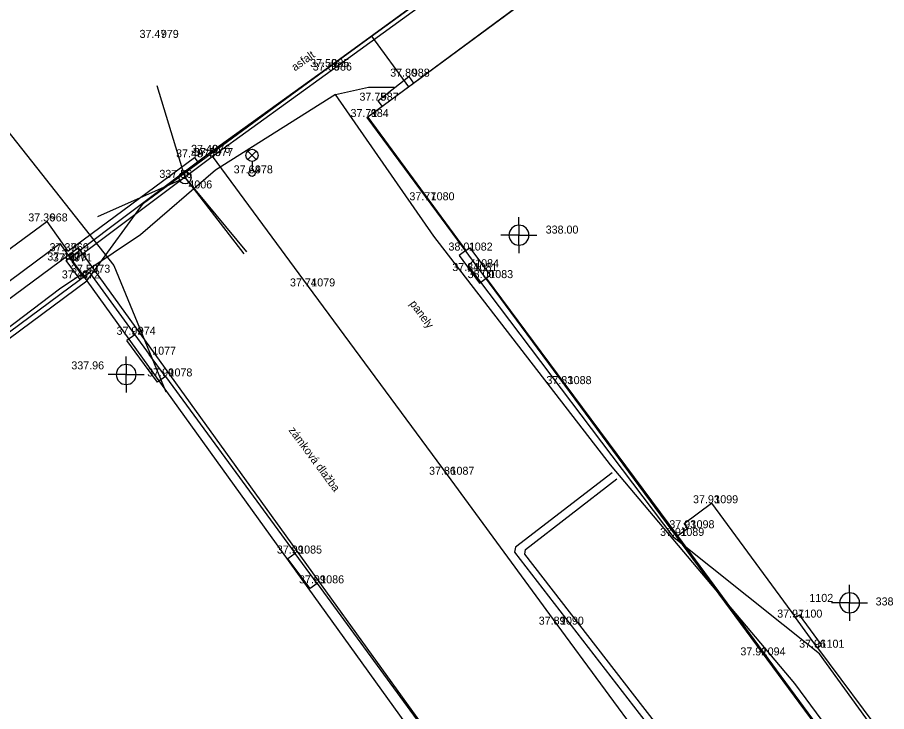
# Model space of a CAD drawing. Extents: x -609709 to -609357, y -1051535 to -1051131.
# Drawn here: x -609584.85 to -609557.69, y -1051267.96 to -1051246.29 of the extents above; entities that cross this region are included whole.
import ezdxf

# ---------------------------------------------------------------- set-up
doc = ezdxf.new("R2010")
doc.units = 0
for name, color, linetype in [('Vrstva 1', 7, 'Continuous'), ('Vrstva 10', 7, 'Continuous'), ('Vrstva 12', 7, 'Continuous'), ('Vrstva 15', 7, 'Continuous'), ('Vrstva 18', 7, 'Continuous'), ('Vrstva 19', 7, 'Continuous'), ('Vrstva 2', 7, 'Continuous'), ('Vrstva 3', 7, 'Continuous'), ('Vrstva 4', 7, 'Continuous'), ('Vrstva 5', 7, 'Continuous'), ('Vrstva 9', 7, 'Continuous')]:
    doc.layers.add(name, color=color, linetype=linetype)

msp = doc.modelspace()

# ---------------------------------------------------------------- linework, layer by layer
at = {"layer": 'Vrstva 1'}
for p, q in [((-609580.46, -1051246.93), (-609580.46, -1051246.93)), ((-609575.13, -1051247.84), (-609575.13, -1051247.84)), ((-609575.05, -1051247.95), (-609575.05, -1051247.95)), ((-609572.62, -1051248.14), (-609572.62, -1051248.14)), ((-609573.59, -1051248.89), (-609573.59, -1051248.89)), ((-609573.9, -1051249.4), (-609573.9, -1051249.4)), ((-609579.32, -1051250.66), (-609579.32, -1051250.66)), ((-609578.85, -1051250.52), (-609578.85, -1051250.52)), ((-609578.76, -1051250.62), (-609578.76, -1051250.62)), ((-609579.61, -1051251.3), (-609579.61, -1051251.3)), ((-609577.52, -1051251.16), (-609577.52, -1051251.16)), ((-609572.03, -1051252), (-609572.03, -1051252)), ((-609583.93, -1051252.66), (-609583.93, -1051252.66)), ((-609583.27, -1051253.59), (-609583.27, -1051253.59)), ((-609570.84, -1051253.57), (-609570.84, -1051253.57)), ((-609583.33, -1051253.88), (-609583.33, -1051253.88)), ((-609583.17, -1051253.91), (-609583.17, -1051253.91)), ((-609582.6, -1051254.26), (-609582.6, -1051254.26)), ((-609570.69, -1051254.21), (-609570.69, -1051254.21)), ((-609570.64, -1051254.09), (-609570.64, -1051254.09)), ((-609582.92, -1051254.44), (-609582.92, -1051254.44)), ((-609570.2, -1051254.43), (-609570.2, -1051254.43)), ((-609575.76, -1051254.69), (-609575.76, -1051254.69)), ((-609581.18, -1051256.2), (-609581.18, -1051256.2)), ((-609580.73, -1051256.82), (-609580.73, -1051256.82)), ((-609580.22, -1051257.5), (-609580.22, -1051257.5)), ((-609567.75, -1051257.74), (-609567.75, -1051257.74)), ((-609571.41, -1051260.57), (-609571.41, -1051260.57)), ((-609563.17, -1051261.46), (-609563.17, -1051261.46)), ((-609563.91, -1051262.24), (-609563.91, -1051262.24)), ((-609564.23, -1051262.48), (-609564.23, -1051262.48)), ((-609576.17, -1051263.03), (-609576.17, -1051263.03)), ((-609575.48, -1051263.96), (-609575.48, -1051263.96)), ((-609560.2, -1051264.54), (-609560.2, -1051264.54)), ((-609560.54, -1051265.03), (-609560.54, -1051265.03)), ((-609567.99, -1051265.25), (-609567.99, -1051265.25)), ((-609559.85, -1051265.97), (-609559.85, -1051265.97)), ((-609561.69, -1051266.21), (-609561.69, -1051266.21))]:
    msp.add_line(p, q, dxfattribs=at)
at = {"layer": 'Vrstva 10'}
for p, q in [((-609572.63, -1051248.46), (-609554.21, -1051234.86)), ((-609573.79, -1051246.88), (-609563.7, -1051239.52)), ((-609576.33, -1051248.73), (-609573.79, -1051246.88)), ((-609573.79, -1051246.88), (-609572.63, -1051248.46)), ((-609573.93, -1051249.42), (-609572.63, -1051248.46)), ((-609580.91, -1051252.09), (-609576.33, -1051248.73)), ((-609573.93, -1051249.42), (-609542.5, -1051291.94)), ((-609582.44, -1051254.19), (-609580.91, -1051252.09)), ((-609592.44, -1051259.93), (-609583.52, -1051253.35)), ((-609583.52, -1051253.35), (-609583.26, -1051253.71)), ((-609583.26, -1051253.71), (-609582.95, -1051253.48)), ((-609582.95, -1051253.48), (-609582.44, -1051254.19)), ((-609592.16, -1051260.28), (-609583.26, -1051253.71)), ((-609583.26, -1051253.71), (-609582.68, -1051254.52)), ((-609582.68, -1051254.52), (-609582.44, -1051254.19)), ((-609582.44, -1051254.19), (-609567.15, -1051275.38)), ((-609591.54, -1051261.06), (-609582.68, -1051254.52)), ((-609582.68, -1051254.52), (-609568.06, -1051274.81))]:
    msp.add_line(p, q, dxfattribs=at)
at = {"layer": 'Vrstva 12'}
for points in [[(-609617.53, -1051308.92), (-609614.08, -1051306.67), (-609612.94, -1051305.52), (-609610.39, -1051304.93), (-609608.61, -1051303.76), (-609606.06, -1051302.68), (-609604.05, -1051302.21), (-609601.38, -1051301.86), (-609597.07, -1051299.84), (-609592.58, -1051298), (-609588.06, -1051296.22), (-609585.76, -1051295.02), (-609575.12, -1051289.04), (-609565.28, -1051281.43), (-609560.89, -1051277.53), (-609555.76, -1051273.58), (-609560.56, -1051267.09), (-609566.32, -1051260.26), (-609571.84, -1051253.12), (-609574.91, -1051248.7), (-609573.88, -1051248.47), (-609573.078, -1051248.47)], [(-609574.91, -1051248.7), (-609578.66, -1051251.06), (-609581, -1051253.08), (-609583.53, -1051254.78), (-609590.25, -1051259.86), (-609592.49, -1051260.08), (-609598.88, -1051264.1), (-609597.705, -1051265.378)]]:
    msp.add_lwpolyline(points, dxfattribs=at)
at = {"layer": 'Vrstva 15'}
for points in [[(-609537.51, -1051208.58), (-609541.98, -1051211.54), (-609559.34, -1051222.57), (-609563.62, -1051224.83), (-609573.15, -1051229.82), (-609581.51, -1051234.92), (-609583.83, -1051237.49), (-609593.84, -1051247.18), (-609592.54, -1051249), (-609587.23, -1051247.57), (-609586.1, -1051248.66), (-609581.84, -1051254.04), (-609580.215, -1051257.976)], [(-609593.36, -1051298.96), (-609591.75, -1051296.49), (-609586.64, -1051293.9), (-609582.17, -1051291.76), (-609577.67, -1051289.07), (-609573.76, -1051285.96), (-609563.26, -1051277.78), (-609562.08, -1051276.96), (-609561.48, -1051274.88), (-609557.22, -1051270.74), (-609556.98, -1051270.04), (-609559.79, -1051266.16), (-609564.332, -1051262.54), (-609570.76, -1051254.05), (-609570.582, -1051253.853)]]:
    msp.add_lwpolyline(points, dxfattribs=at)
at = {"layer": 'Vrstva 18'}
for points in [[(-609579.61, -1051251.3), (-609580.483, -1051248.43)], [(-609579.61, -1051251.3), (-609582.351, -1051252.52)], [(-609579.61, -1051251.3), (-609577.773, -1051253.672)], [(-609579.61, -1051251.3), (-609577.697, -1051253.611)]]:
    msp.add_lwpolyline(points, dxfattribs=at)
for radius in [0.188, 0.025]:
    msp.add_circle((-609579.61, -1051251.3), radius, dxfattribs=at)
at = {"layer": 'Vrstva 19'}
for points in [[(-609566.27, -1051260.51), (-609569.29, -1051262.83), (-609569.32, -1051262.99), (-609565.43, -1051268.02), (-609561.43, -1051273.16), (-609561.44, -1051273.3), (-609561.81, -1051273.58)], [(-609589.68, -1051320.38), (-609591.1, -1051321.45), (-609591.26, -1051321.42), (-609595.66, -1051315.54), (-609599.29, -1051310.59), (-609603.57, -1051304.6), (-609603.53, -1051304.45), (-609597.5, -1051300.05), (-609589.44, -1051294.18), (-609579.1, -1051286.55), (-609565.69, -1051276.62), (-609561.84, -1051273.9), (-609561.08, -1051273.38), (-609561.07, -1051273.26), (-609565.31, -1051267.81), (-609569, -1051263.05), (-609568.98, -1051262.9), (-609566.12, -1051260.7)]]:
    msp.add_lwpolyline(points, dxfattribs=at)
at = {"layer": 'Vrstva 4'}
for points in [[(-609582.893, -1051254.477), (-609583.33, -1051253.88), (-609578.85, -1051250.52), (-609575.13, -1051247.84), (-609572.3, -1051245.78), (-609567.76, -1051242.48), (-609563.69, -1051239.47), (-609566.83, -1051234.72), (-609570.26, -1051237.06), (-609574.4, -1051239.86)], [(-609582.781, -1051254.394), (-609583.135, -1051253.909), (-609578.767, -1051250.633), (-609575.048, -1051247.953), (-609572.218, -1051245.893), (-609567.677, -1051242.593), (-609563.5, -1051239.504), (-609566.792, -1051234.524), (-609570.339, -1051236.944), (-609574.468, -1051239.737)], [(-609594.374, -1051255.045), (-609591.8, -1051258.51), (-609589.06, -1051256.43), (-609583.93, -1051252.66), (-609583.27, -1051253.59), (-609579.32, -1051250.66), (-609579.218, -1051250.796)], [(-609569.78, -1051291.945), (-609565.31, -1051288.54), (-609560.44, -1051284.98), (-609557.77, -1051283.08), (-609557.43, -1051283.26), (-609555.58, -1051282.04), (-609559.96, -1051276.13), (-609563.31, -1051271.56), (-609565.26, -1051268.95), (-609567.99, -1051265.25), (-609571.41, -1051260.57), (-609575.76, -1051254.69), (-609578.756, -1051250.625)]]:
    msp.add_lwpolyline(points, dxfattribs=at)
at = {"layer": 'Vrstva 5'}
for p, q in [((-609577.652, -1051250.73), (-609577.388, -1051250.465)), ((-609577.652, -1051250.465), (-609577.388, -1051250.73)), ((-609577.52, -1051250.785), (-609577.52, -1051251.06))]:
    msp.add_line(p, q, dxfattribs=at)
for centre, radius in [((-609577.52, -1051250.597), 0.188), ((-609577.52, -1051251.16), 0.1)]:
    msp.add_circle(centre, radius, dxfattribs=at)
at = {"layer": 'Vrstva 9'}
for p, q in [((-609569.18, -1051252.778), (-609569.18, -1051252.528)), ((-609569.493, -1051253.09), (-609569.743, -1051253.09)), ((-609568.868, -1051253.09), (-609568.618, -1051253.09)), ((-609569.18, -1051253.403), (-609569.18, -1051253.653)), ((-609581.45, -1051257.127), (-609581.45, -1051256.877)), ((-609581.763, -1051257.44), (-609582.013, -1051257.44)), ((-609581.138, -1051257.44), (-609580.888, -1051257.44)), ((-609581.45, -1051257.752), (-609581.45, -1051258.002)), ((-609558.85, -1051264.258), (-609558.85, -1051264.008)), ((-609559.162, -1051264.57), (-609559.412, -1051264.57)), ((-609558.537, -1051264.57), (-609558.287, -1051264.57)), ((-609558.85, -1051264.883), (-609558.85, -1051265.133))]:
    msp.add_line(p, q, dxfattribs=at)
for points in [[(-609558.64, -1051238.12), (-609573.9, -1051249.4), (-609570.84, -1051253.57)], [(-609573.59, -1051248.89), (-609572.62, -1051248.14), (-609572.47, -1051248.343)], [(-609573.59, -1051248.89), (-609573.457, -1051249.07)], [(-609569.18, -1051252.778), (-609569.18, -1051253.09), (-609568.868, -1051253.09)], [(-609569.18, -1051253.403), (-609569.18, -1051253.09), (-609569.493, -1051253.09)], [(-609570.84, -1051253.57), (-609570.719, -1051253.481)], [(-609570.719, -1051253.481), (-609570.079, -1051254.341)], [(-609571.05, -1051253.724), (-609570.411, -1051254.586)], [(-609570.84, -1051253.57), (-609571.048, -1051253.722)], [(-609585.71, -1051256.56), (-609582.6, -1051254.26), (-609581.18, -1051256.2), (-609580.73, -1051256.82)], [(-609570.411, -1051254.586), (-609570.2, -1051254.43)], [(-609570.2, -1051254.43), (-609570.079, -1051254.341)], [(-609570.2, -1051254.43), (-609567.75, -1051257.74), (-609564.23, -1051262.48), (-609563.91, -1051262.24)], [(-609581.18, -1051256.2), (-609581.43, -1051256.383)], [(-609580.47, -1051257.683), (-609581.43, -1051256.383)], [(-609580.22, -1051257.5), (-609580.73, -1051256.82)], [(-609581.45, -1051257.127), (-609581.45, -1051257.44), (-609581.138, -1051257.44)], [(-609581.45, -1051257.752), (-609581.45, -1051257.44), (-609581.763, -1051257.44)], [(-609580.22, -1051257.5), (-609580.47, -1051257.683)], [(-609580.22, -1051257.5), (-609576.17, -1051263.03)], [(-609563.91, -1051262.24), (-609564.018, -1051262.096), (-609563.17, -1051261.46), (-609560.54, -1051265.03)], [(-609564.23, -1051262.48), (-609542.85, -1051291.49)], [(-609576.17, -1051263.03), (-609576.396, -1051263.195)], [(-609575.706, -1051264.125), (-609576.396, -1051263.195)], [(-609575.48, -1051263.96), (-609576.17, -1051263.03)], [(-609575.48, -1051263.96), (-609575.706, -1051264.125)], [(-609575.48, -1051263.96), (-609567.59, -1051274.75), (-609570.66, -1051277)], [(-609558.85, -1051264.258), (-609558.85, -1051264.57), (-609558.537, -1051264.57)], [(-609558.85, -1051264.883), (-609558.85, -1051264.57), (-609559.162, -1051264.57)], [(-609560.54, -1051265.03), (-609560.42, -1051264.941)], [(-609559.85, -1051265.97), (-609560.54, -1051265.03)], [(-609559.73, -1051265.881), (-609560.42, -1051264.941)], [(-609559.85, -1051265.97), (-609559.73, -1051265.881)], [(-609559.85, -1051265.97), (-609557.7, -1051268.87)]]:
    msp.add_lwpolyline(points, dxfattribs=at)
for centre, start, end in [((-609569.18, -1051253.09), 90, 180), ((-609569.18, -1051253.09), 0, 90), ((-609569.18, -1051253.09), 180, 270), ((-609569.18, -1051253.09), 270, 0), ((-609581.45, -1051257.44), 90, 180), ((-609581.45, -1051257.44), 0, 90), ((-609581.45, -1051257.44), 180, 270), ((-609581.45, -1051257.44), 270, 0), ((-609558.85, -1051264.57), 90, 180), ((-609558.85, -1051264.57), 0, 90), ((-609558.85, -1051264.57), 180, 270), ((-609558.85, -1051264.57), 270, 0)]:
    msp.add_arc(centre, 0.312, start, end, dxfattribs=at)

# ---------------------------------------------------------------- texts
at = {"layer": 'Vrstva 18'}
msp.add_text(' 4006', height=0.25, dxfattribs=at).set_placement((-609579.6, -1051251.63))
at = {"layer": 'Vrstva 2'}
for s, p in [(' 979', (-609580.46, -1051246.93)), (' 985', (-609575.13, -1051247.84)), (' 986', (-609575.05, -1051247.95)), (' 988', (-609572.62, -1051248.14)), (' 987', (-609573.59, -1051248.89)), (' 984', (-609573.9, -1051249.4)), (' 975', (-609579.32, -1051250.66)), (' 976', (-609578.85, -1051250.52)), (' 977', (-609578.76, -1051250.62)), (' 978', (-609577.52, -1051251.16)), (' 1080', (-609572.03, -1051252)), (' 968', (-609583.93, -1051252.66)), (' 969', (-609583.27, -1051253.59)), (' 1082', (-609570.84, -1051253.57)), (' 970', (-609583.33, -1051253.88)), (' 971', (-609583.17, -1051253.91)), (' 973', (-609582.6, -1051254.26)), (' 1081', (-609570.69, -1051254.21)), (' 1084', (-609570.64, -1051254.09)), (' 972', (-609582.92, -1051254.44)), (' 1083', (-609570.2, -1051254.43)), (' 1079', (-609575.76, -1051254.69)), (' 974', (-609581.18, -1051256.2)), (' 1077', (-609580.73, -1051256.82)), (' 1078', (-609580.22, -1051257.5)), (' 1088', (-609567.75, -1051257.74)), (' 1087', (-609571.41, -1051260.57)), (' 1099', (-609563.17, -1051261.46)), (' 1098', (-609563.91, -1051262.24)), (' 1089', (-609564.23, -1051262.48)), (' 1085', (-609576.17, -1051263.03)), (' 1086', (-609575.48, -1051263.96)), (' 1102', (-609560.2, -1051264.54)), (' 1100', (-609560.54, -1051265.03)), (' 1090', (-609567.99, -1051265.25)), (' 1094', (-609561.69, -1051266.21)), (' 1101', (-609559.85, -1051265.97))]:
    msp.add_text(s, height=0.25, dxfattribs=at).set_placement(p)
at = {"layer": 'Vrstva 3'}
for s, p in [('37.47', (-609581.033, -1051246.93)), ('37.59', (-609575.703, -1051247.84)), ('37.69', (-609575.623, -1051247.95)), ('37.80', (-609573.203, -1051248.14)), ('37.75', (-609574.163, -1051248.89)), ('37.71', (-609574.442, -1051249.4)), ('37.48', (-609579.893, -1051250.66)), ('37.49', (-609579.423, -1051250.52)), ('37.59', (-609579.333, -1051250.62)), ('37.64', (-609578.093, -1051251.16)), ('337.56', (-609580.414, -1051251.3)), ('37.77', (-609572.603, -1051252)), ('37.36', (-609584.509, -1051252.66)), ('338.00', (-609568.346, -1051253.04)), ('37.37', (-609583.843, -1051253.59)), ('38.01', (-609571.382, -1051253.57)), ('37.40', (-609583.913, -1051253.88)), ('37.47', (-609583.743, -1051253.91)), ('37.59', (-609583.173, -1051254.26)), ('37.84', (-609571.263, -1051254.21)), ('37.41', (-609583.462, -1051254.44)), ('38.00', (-609570.783, -1051254.43)), ('37.74', (-609576.333, -1051254.69)), ('37.92', (-609581.753, -1051256.2)), ('337.96', (-609583.164, -1051257.28)), ('37.99', (-609580.793, -1051257.5)), ('37.83', (-609568.323, -1051257.74)), ('37.86', (-609571.989, -1051260.57)), ('37.93', (-609563.743, -1051261.46)), ('37.93', (-609564.483, -1051262.24)), ('37.91', (-609564.772, -1051262.48)), ('37.99', (-609576.743, -1051263.03)), ('37.99', (-609576.053, -1051263.96)), ('338.05', (-609558.038, -1051264.65)), ('37.97', (-609561.113, -1051265.03)), ('37.89', (-609568.563, -1051265.25)), ('37.92', (-609562.263, -1051266.21)), ('37.96', (-609560.429, -1051265.97))]:
    msp.add_text(s, height=0.25, dxfattribs=at).set_placement(p)
at = {"layer": 'Vrstva 4'}
for s, rotation, p in [('asfalt', 35.7701, (-609576.179, -1051247.979)), ('panely', 306.4939, (-609572.607, -1051255.233)), ('zámková dlažba', 306.4939, (-609576.388, -1051259.183))]:
    msp.add_text(s, height=0.25, rotation=rotation, dxfattribs=at).set_placement(p)

doc.saveas('drawing.dxf')
